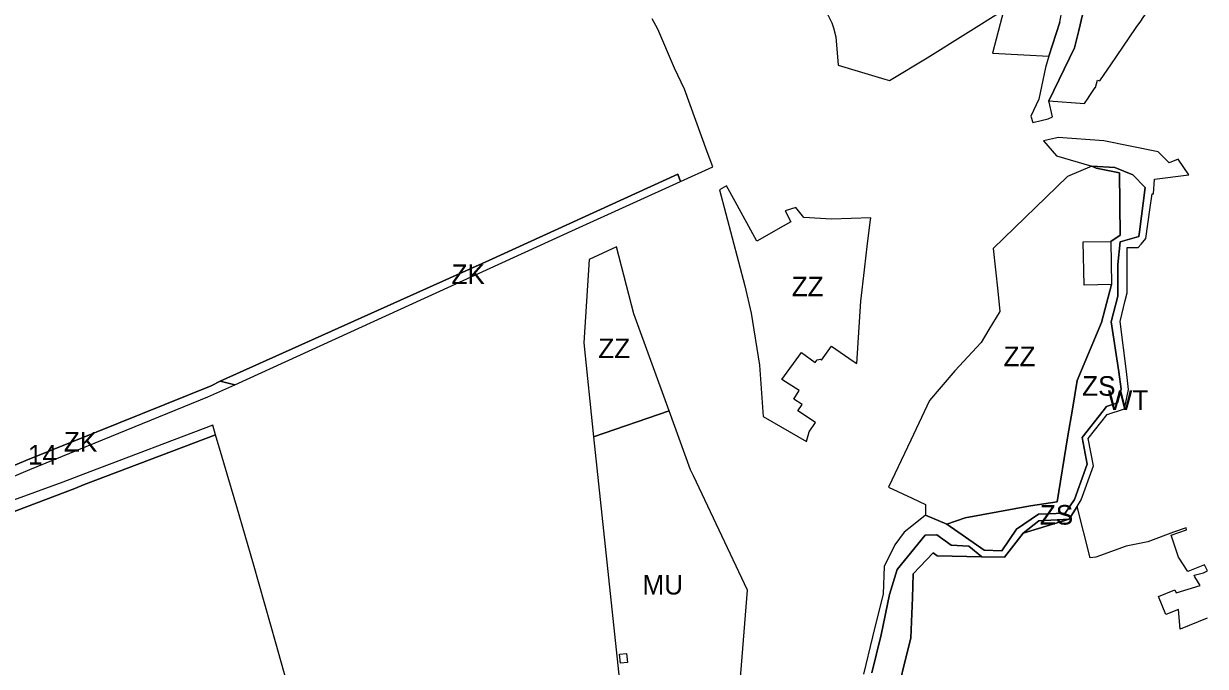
# Model space of a CAD drawing. Extents: x -522079 to -518833, y -1142398 to -1139961.
# Drawn here: x -520990 to -520386, y -1141061 to -1140733 of the extents above; entities that cross this region are included whole.
import ezdxf

# ---------------------------------------------------------------- set-up
doc = ezdxf.new("R2010")
doc.units = 0
for name, color, linetype in [('90640013', 7, 'Continuous'), ('90660013', 7, 'Continuous'), ('90670013', 7, 'Continuous'), ('90710013', 7, 'Continuous'), ('90710023', 7, 'Continuous'), ('90750013', 7, 'Continuous'), ('90830013', 7, 'Continuous'), ('ID_navrh', 7, 'Continuous')]:
    doc.layers.add(name, color=color, linetype=linetype)

msp = doc.modelspace()

# ---------------------------------------------------------------- linework, layer by layer
at = {"layer": '90640013'}
for points in [[(-520460.77, -1140732), (-520466.36, -1140749.44), (-520468.2, -1140755.18), (-520471.47, -1140771.35), (-520475.64, -1140780.08), (-520474.64, -1140783.36), (-520470.41, -1140782.37), (-520466.78, -1140781.53), (-520464.48, -1140780.47), (-520466.39, -1140772.32), (-520453.26, -1140745.12), (-520451.15, -1140736.24), (-520445.6, -1140712.87)], [(-520556.84, -1141064.48), (-520552.06, -1141045.13), (-520547.82, -1141024.57), (-520543.9, -1141011.82), (-520529.65, -1140994.14), (-520523.73, -1140993.96), (-520516.37, -1140999.34), (-520507.31, -1140999.82), (-520500.6, -1141005.26), (-520489.07, -1141005.5), (-520479.55, -1140993.19), (-520471.51, -1140986.91), (-520456.05, -1140986), (-520451.99, -1140979.48), (-520449.86, -1140976.07), (-520443.57, -1140958.81), (-520446.27, -1140944.76), (-520436.62, -1140932.6), (-520427.82, -1140929.68), (-520425.67, -1140919.72), (-520426.8, -1140910.65), (-520429.99, -1140884.98), (-520427.4, -1140874.32), (-520426.37, -1140870.34), (-520426.43, -1140847.27), (-520420.69, -1140847.27), (-520419.27, -1140845.56), (-520416.81, -1140842.62), (-520414.81, -1140828.01), (-520413.68, -1140819.71), (-520412.85, -1140819.83), (-520412.34, -1140812.28), (-520394.93, -1140810.08), (-520400.31, -1140802.09), (-520404.93, -1140803.86), (-520410.6, -1140798.4), (-520438.34, -1140792.64), (-520461.64, -1140791.05), (-520463.08, -1140791.37), (-520469.2, -1140792.72), (-520462.48, -1140800.42), (-520444.45, -1140805.57), (-520432.63, -1140806.38), (-520423.57, -1140810.07), (-520417.22, -1140816.48), (-520420.15, -1140839.19), (-520420.46, -1140841.58), (-520429.98, -1140844.23), (-520431.21, -1140855.94), (-520431.14, -1140872), (-520434.57, -1140885.18), (-520430.59, -1140910.8), (-520429.5, -1140919.57), (-520431.36, -1140926.59), (-520436.87, -1140928.43), (-520438.64, -1140930.72), (-520449.47, -1140944.32), (-520446.79, -1140958), (-520453.28, -1140975.93), (-520458.05, -1140982.9), (-520471.76, -1140983.46), (-520483.03, -1140991.17), (-520490.41, -1141002.21), (-520499.42, -1141001.88), (-520518.62, -1140988.49), (-520529.52, -1140984.06), (-520536.52, -1140989.65)], [(-520536.52, -1140989.65), (-520540.36, -1140992.71), (-520545.15, -1140999.12), (-520550.66, -1141010.15), (-520551.07, -1141024.16), (-520556.5, -1141046.1), (-520561.24, -1141065.24)]]:
    msp.add_lwpolyline(points, dxfattribs=at)
at = {"layer": '90660013'}
for points in [[(-520518.62, -1140988.49), (-520499.42, -1141001.88), (-520490.41, -1141002.21), (-520483.03, -1140991.17), (-520471.76, -1140983.46), (-520458.05, -1140982.9), (-520453.28, -1140975.93), (-520446.79, -1140958), (-520449.47, -1140944.32), (-520438.64, -1140930.72), (-520436.87, -1140928.43), (-520431.36, -1140926.59), (-520429.5, -1140919.57), (-520430.59, -1140910.8), (-520434.57, -1140885.18), (-520431.14, -1140872), (-520431.21, -1140855.94), (-520429.98, -1140844.23), (-520420.46, -1140841.58), (-520420.15, -1140839.19), (-520417.22, -1140816.48), (-520423.57, -1140810.07), (-520432.63, -1140806.38), (-520444.45, -1140805.57), (-520442.16, -1140806.74), (-520430.39, -1140809.03), (-520430.02, -1140840.87), (-520434.81, -1140844.08), (-520434.39, -1140866.1), (-520439.44, -1140885.49), (-520451.95, -1140915.2), (-520454.37, -1140929.78), (-520456.82, -1140944.51), (-520462.25, -1140977.23), (-520475.75, -1140979.18), (-520509.19, -1140985.26), (-520518.62, -1140988.49)], [(-520479.55, -1140993.19), (-520456.05, -1140986), (-520471.51, -1140986.91), (-520479.55, -1140993.19)], [(-520500.6, -1141005.26), (-520507.31, -1140999.82), (-520516.37, -1140999.34), (-520523.73, -1140993.96), (-520529.65, -1140994.14), (-520543.9, -1141011.82), (-520547.82, -1141024.57), (-520552.06, -1141045.13), (-520556.84, -1141064.48)], [(-520545.68, -1141081.75), (-520537, -1141046.7), (-520536.12, -1141026.2), (-520535.76, -1141013.89), (-520525.61, -1141003.28), (-520523.55, -1141004.78), (-520500.6, -1141005.26)]]:
    msp.add_lwpolyline(points, dxfattribs=at)
at = {"layer": '90670013'}
for points in [[(-520481.74, -1140636.06), (-520493.55, -1140626.8), (-520598.21, -1140690.89), (-520586.97, -1140713.22), (-520580.64, -1140725.97), (-520577.29, -1140732.42), (-520576.44, -1140734.91), (-520575.25, -1140739.5), (-520574.04, -1140754.01), (-520550.23, -1140761.11), (-520547.81, -1140761.83), (-520528.59, -1140750.29), (-520489.4, -1140725.83), (-520495.27, -1140747.98), (-520479.24, -1140748.79), (-520466.36, -1140749.44), (-520460.77, -1140732), (-520457.2, -1140712.56), (-520457.81, -1140671.57), (-520481.74, -1140636.06)], [(-520442.27, -1140685.74), (-520445.6, -1140712.87), (-520451.15, -1140736.24), (-520453.26, -1140745.12), (-520466.39, -1140772.32), (-520448.2, -1140773.61), (-520446.34, -1140770.88), (-520445.76, -1140770.03), (-520442.66, -1140765.49), (-520442.65, -1140765.47), (-520441.56, -1140761.77), (-520440.36, -1140762.11), (-520434.44, -1140753.41), (-520431.9, -1140749.57), (-520421.72, -1140734.81), (-520419.44, -1140731.56), (-520418.13, -1140729.68), (-520414.39, -1140724.32), (-520422.23, -1140704.1), (-520427.81, -1140690.88), (-520432.59, -1140679.54), (-520442.27, -1140685.74)], [(-520434.81, -1140844.08), (-520430.02, -1140840.87), (-520430.39, -1140809.03), (-520442.16, -1140806.74), (-520444.45, -1140805.57), (-520456.93, -1140810.9), (-520494.89, -1140847.8), (-520492.53, -1140869.55), (-520491.41, -1140879.85), (-520497.04, -1140889.19), (-520500.98, -1140895.73), (-520514.41, -1140910.27), (-520527.38, -1140925.42), (-520536.98, -1140945.57), (-520548.43, -1140969.6), (-520536.34, -1140975.31), (-520529.45, -1140978.56), (-520529.52, -1140984.06), (-520518.62, -1140988.49), (-520509.19, -1140985.26), (-520475.75, -1140979.18), (-520462.25, -1140977.23), (-520456.82, -1140944.51), (-520454.37, -1140929.78), (-520451.95, -1140915.2), (-520439.44, -1140885.49), (-520434.39, -1140866.1), (-520448.4, -1140866.37), (-520448.82, -1140844.35), (-520434.81, -1140844.08)], [(-520660.47, -1140930.63), (-520678.48, -1140881.15), (-520687.49, -1140846.81), (-520701.37, -1140853.35), (-520704.17, -1140895.93), (-520699.09, -1140943.92), (-520660.47, -1140930.63)], [(-520385.48, -1141036.63), (-520399.24, -1141042.3), (-520400.21, -1141032.13), (-520406.62, -1141034.69), (-520410.31, -1141025.45), (-520401.95, -1141022.11), (-520401.32, -1141023.68), (-520389.08, -1141019.93), (-520391.74, -1141015.46), (-520392.22, -1141014.66), (-520387.31, -1141013.36), (-520385.38, -1141012.44), (-520386.94, -1141009.33), (-520395.43, -1141012.8), (-520400.21, -1141005.43), (-520403.95, -1140994.2), (-520400.05, -1140992.89), (-520396.06, -1140991.53), (-520396.26, -1140990.46), (-520402.73, -1140992.69), (-520415.87, -1140997.65), (-520426.91, -1140999.86), (-520442.37, -1141005.47), (-520445.36, -1141005.71), (-520451.99, -1140979.48), (-520456.05, -1140986), (-520479.55, -1140993.19)], [(-520479.55, -1140993.19), (-520489.07, -1141005.5), (-520500.6, -1141005.26), (-520523.55, -1141004.78), (-520525.61, -1141003.28), (-520535.76, -1141013.89), (-520536.12, -1141026.2), (-520537, -1141046.7), (-520545.68, -1141081.75)]]:
    msp.add_lwpolyline(points, dxfattribs=at)
msp.add_lwpolyline([(-520634.79, -1140817.77), (-520621.9, -1140866.86), (-520618.56, -1140880.81), (-520614.37, -1140907.34), (-520612.5, -1140933.48), (-520590.36, -1140946.34), (-520588.9, -1140941.38), (-520585.74, -1140936.61), (-520594.7, -1140930.72), (-520592.56, -1140927.47), (-520596.85, -1140924.77), (-520594.01, -1140920.33), (-520602.83, -1140914.7), (-520592.91, -1140900.92), (-520585.91, -1140906.02), (-520584.9, -1140904.6), (-520583.16, -1140904.29), (-520582.61, -1140904.74), (-520577.55, -1140897.54), (-520566.38, -1140905.28), (-520564.56, -1140906.56), (-520562.5, -1140874.6), (-520560.66, -1140858.55), (-520559.8, -1140851.08), (-520559.29, -1140846.65), (-520557.73, -1140834.26), (-520557.47, -1140832.08), (-520577.54, -1140832.73), (-520591.61, -1140831.81), (-520595.7, -1140826.74), (-520601.28, -1140828.55), (-520598.3, -1140834.1), (-520602.23, -1140836.31), (-520615.7, -1140843.89), (-520626.71, -1140823.74), (-520631.12, -1140815.76)], close=True, dxfattribs=at)
at = {"layer": '90710013'}
msp.add_lwpolyline([(-520882.47, -1140917.37), (-520708.35, -1140837.86), (-520654.73, -1140813.47), (-520656.02, -1140809.72), (-520752.69, -1140853.85), (-520890.08, -1140915.49)], close=True, dxfattribs=at)
at = {"layer": '90710023'}
msp.add_lwpolyline([(-521082.3, -1140995.42), (-521081.12, -1140996.97), (-521077.97, -1140999.02), (-520987.34, -1140960.66), (-520896.33, -1140923.45), (-520882.47, -1140917.37), (-520890.08, -1140915.49), (-520894.6, -1140917.89), (-520989.26, -1140956.04)], close=True, dxfattribs=at)
msp.add_lwpolyline([(-521190.59, -1141062.63), (-521154.28, -1141046.62), (-521111.47, -1141027.75), (-521085.77, -1141016.42), (-520964.29, -1140970.32), (-520959.78, -1140968.46), (-520892.3, -1140942.89), (-520893.74, -1140937.98), (-520956.56, -1140961.79), (-520970.5, -1140967.09), (-521026.59, -1140987.63), (-521082.18, -1141009.47), (-521112.83, -1141022.98), (-521155.63, -1141041.85), (-521191.96, -1141057.88), (-521222.3, -1141071.25)], dxfattribs=at)
at = {"layer": '90750013'}
msp.add_lwpolyline([(-521082.3, -1140995.42), (-520989.26, -1140956.04), (-520894.6, -1140917.89), (-520890.08, -1140915.49), (-520752.69, -1140853.85), (-520656.02, -1140809.72), (-520654.73, -1140813.47), (-520638.22, -1140805.93), (-520641.11, -1140798.37), (-520652.69, -1140766.32), (-520657.82, -1140755.57), (-520666.3, -1140735.71), (-520669.12, -1140730.36)], dxfattribs=at)
msp.add_lwpolyline([(-520727.16, -1141148.38), (-520733.88, -1141082.24), (-520846.14, -1141104.23), (-520847.24, -1141100.33), (-520861.45, -1141049.84), (-520872.93, -1141009.05), (-520881.52, -1140979.72), (-520885.58, -1140965.84), (-520888.93, -1140954.41), (-520892.3, -1140942.89), (-520959.78, -1140968.46), (-520964.29, -1140970.32), (-521085.77, -1141016.42), (-521111.47, -1141027.75), (-521154.28, -1141046.62), (-521190.59, -1141062.63), (-521216.29, -1141073.97), (-521143.42, -1141331.19), (-521117.38, -1141319.6), (-521081.35, -1141303.56), (-521038.45, -1141284.46), (-520895.96, -1141221.04), (-520890.16, -1141218.54)], close=True, dxfattribs=at)
at = {"layer": '90830013'}
for points in [[(-520649.51, -1140960.76), (-520660.47, -1140930.63), (-520699.09, -1140943.92), (-520679.92, -1141124.76), (-520676.95, -1141126.77), (-520627.13, -1141105.32), (-520620.51, -1141022.34), (-520648.03, -1140963.9), (-520649.51, -1140960.76)], [(-520681.75, -1141059.18), (-520685.33, -1141059.63), (-520685.9, -1141055.06), (-520682.32, -1141054.61), (-520681.75, -1141059.18)]]:
    msp.add_lwpolyline(points, dxfattribs=at)

# ---------------------------------------------------------------- texts
at = {"layer": '90640013'}
msp.add_text('WT', height=10, rotation=0, dxfattribs=at).set_placement((-520436.32, -1140930.17))
at = {"layer": '90660013'}
for rotation, p in [(0, (-520449.41, -1140922.95)), (360, (-520471.04, -1140988.8))]:
    msp.add_text('ZS', height=10, rotation=rotation, dxfattribs=at).set_placement(p)
at = {"layer": '90670013'}
for p in [(-520597.87, -1140872.15), (-520696.73, -1140903.75), (-520489.57, -1140907.86)]:
    msp.add_text('ZZ', height=10, rotation=360, dxfattribs=at).set_placement(p)
at = {"layer": '90710013'}
msp.add_text('ZK', height=10, rotation=360, dxfattribs=at).set_placement((-520771.8, -1140865.89))
at = {"layer": '90710023'}
msp.add_text('ZK', height=10, rotation=0, dxfattribs=at).set_placement((-520969.91, -1140951.46))
at = {"layer": '90830013'}
msp.add_text('MU', height=10, rotation=360, dxfattribs=at).set_placement((-520674.18, -1141024.52))
at = {"layer": 'ID_navrh'}
msp.add_text('14', height=10, rotation=360, dxfattribs=at).set_placement((-520988.26, -1140958.12))

doc.saveas('drawing.dxf')
